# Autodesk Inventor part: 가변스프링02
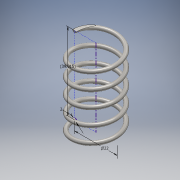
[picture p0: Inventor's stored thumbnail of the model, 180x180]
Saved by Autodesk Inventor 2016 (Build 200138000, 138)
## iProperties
Created: 2015-11
Part Number: 가변스프링02
Material: 스테인레스 스틸
Document SubType Name: Modeling
Designer: eco
Density: 8 g/cm^3
Appearance: 반연마
Mass: 8.59431 g
Surface Area: 21.7367 cm^2
Volume: 1.07429 cm^3
Author: eco
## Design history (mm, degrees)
sketch "스케치1"
  geometry: L1 (0, 0)-(11, 0); L2 (11, 0)-(11, 40.276); L3 (11, 40.276)-(0, 40.276); L4 (0, 40.276)-(0, 0); C1 r 1 at (11, 0)
  constraints: 8 end point, 2 parallel, 1 centre point, 1 coincident, 1 horizontal, 1 perpendicular
  dimensions: "d0" = 2 diameter of C1; "d1" = 22 diameter of L2 L4; "d2" = 40.27636 distance of L1.end L2.end (derived)
feature "코일1" pitch "d3" = 10; turns "d5" = 5; dims "d4" = 40.27636 (= d2), "d6" = 0, angle "d7" = 90 deg, angle "d8" = 90 deg, "d9" = 0, "d10" = 0
sketch "스케치2"
  geometry: L1 (-12, 0)-(-10, 0) reference; 1 further point
  constraints: 1 horizontal alignment
extrude "돌출1" cut sketch "스케치2" stored distance "d11" = 10; taper "d12" = 0 deg
node "작업 평면1"
sketch "스케치3"
  geometry: L1 (1, 0)-(-1, 0) reference; 1 further point
  constraints: 1 horizontal alignment
extrude "돌출2" cut sketch "스케치3" stored distance "d14" = 10; taper "d15" = 0 deg
node "솔리드1"
node "절단 모서리 투영1"
node "절단 모서리 투영2"
other parameters: "d13" = 0
